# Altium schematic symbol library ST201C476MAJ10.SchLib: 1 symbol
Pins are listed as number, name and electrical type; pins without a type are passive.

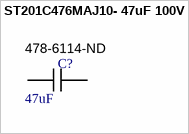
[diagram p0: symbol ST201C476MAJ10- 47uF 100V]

## ST201C476MAJ10- 47uF 100V
designator C?, comment Supplier Part Number: 478-6114-ND  (hidden comment: 47uF)
CAP CER 47UF 100V 20% X7R SMD; Part Number: ST201C476MAJ10; Manufacturer: AVX Corporation; Value: 47µF
footprint AVX-ST20-J10
pins: 1, 2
